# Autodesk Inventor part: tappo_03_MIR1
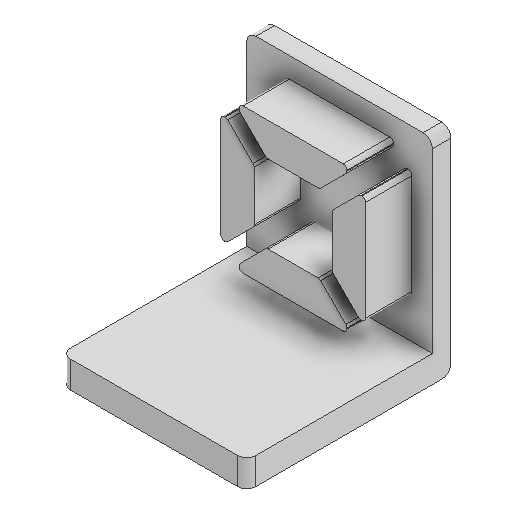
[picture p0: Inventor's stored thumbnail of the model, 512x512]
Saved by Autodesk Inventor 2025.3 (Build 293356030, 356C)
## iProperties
Created: 2026-02
Part Number: tappo_03_MIR1
Material: Generico
Document SubType Name: Modeling
Designer: R5800u
Density: 1 g/cm^3
Appearance: Default
Author: R5800u
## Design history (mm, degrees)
derived "tappo_03.ipt"
  sketch "Schizzo1"
    geometry: L1 (-10, 10)-(10, 10) reference; L2 (10, 10)-(10, -10) reference; L3 (10, -10)-(-10, -10) reference; L4 (-10, -10)-(-10, 10) reference; L5 (-10, 10)-(10, -10) reference; L6 (10, 10)-(-10, -10) reference; L7 (-6, -8)-(-3, -8) reference; L8 (-6, -7.061)-(-6, -8) reference; L9 (-2.939, -4)-(-6, -7.061) reference; L10 (0, 0)-(0, -10) reference; L11 (-2.939, -4)-(0, -4) reference; L12 (-3, -8)-(0, -8) reference; L13 (0, -7.8)-(-3, -7.8) reference; L14 (-3, -7.8)-(-5.8, -7.8) reference; L15 (-5.8, -7.8)-(-5.8, -7.144) reference; L16 (-5.8, -7.144)-(-2.856, -4.2) reference; L17 (-2.856, -4.2)-(0, -4.2) reference; L18 (0, -7.8)-(3, -7.8) reference; L19 (3, -7.8)-(5.8, -7.8) reference; L20 (5.8, -7.8)-(5.8, -7.144) reference; L21 (5.8, -7.144)-(2.856, -4.2) reference; L22 (2.856, -4.2)-(0, -4.2) reference
  sketch "Schizzo2"
    geometry: 1 further point
  sketch "Schizzo3"
    geometry: L1 (0, 0)-(-20, 0) reference; L2 (-20, 0)-(-20, 2) reference; L3 (0, 2)-(-20, 2) reference; L4 (0, 0)-(0, 2) reference; 1 further point
  sketch "Schizzo4"
    geometry: L1 (10, -13)-(-10, -13) reference; L2 (10, 9)-(10, -13) reference; L3 (-10, -13)-(10, -13) reference; L4 (10, -13)-(10, -10.1) reference; L5 (10, -10.1)-(-10, -10.1) reference; L6 (-10, -10.1)-(-10, -13) reference; 1 further point
feature "Solido1::tappo_03.ipt"
feature "Solido2::tappo_03.ipt"
tag "Lavorazione contrassegno1"
node "Solido1"
node "Solido2"
